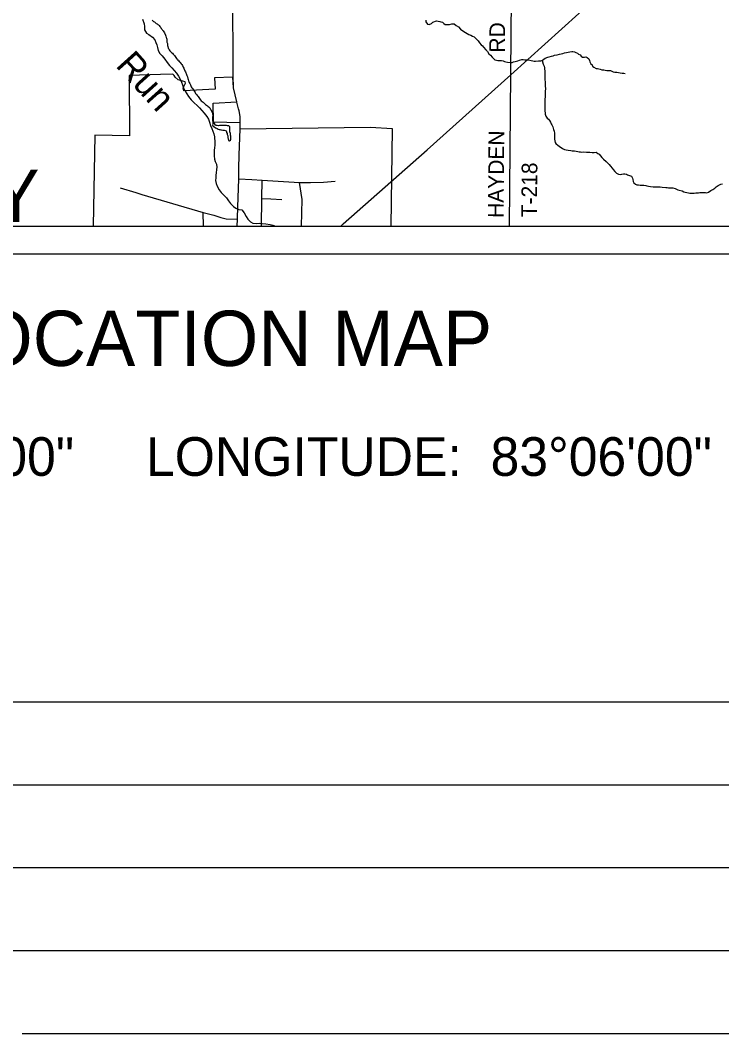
# Model space of a CAD drawing. Extents: x 36.7 to 70.7, y 0 to 22.
# Drawn here: x 41.432 to 43.973, y 11.174 to 14.842 of the extents above; entities that cross this region are included whole.
import ezdxf

# ---------------------------------------------------------------- set-up
doc = ezdxf.new("R2010")
doc.units = 0
for name, color, linetype in [('Default', 7, 'Continuous'), ('GM_X_City_Street', 7, 'Continuous'), ('GM_X_County_Text', 7, 'Continuous'), ('GM_X_Minor_Lake', 7, 'Continuous'), ('GM_X_Minor_River', 7, 'Continuous'), ('GM_X_Minor_River_Text', 7, 'Continuous'), ('GM_X_Rail_Line', 7, 'Continuous'), ('GM_X_State_Route', 7, 'Continuous'), ('GM_X_Township_Road', 7, 'Continuous'), ('GM_X_Township_Road_Text', 7, 'Continuous'), ('SH_Data', 7, 'Continuous'), ('SH_Text', 7, 'Continuous')]:
    doc.layers.add(name, color=color, linetype=linetype)

msp = doc.modelspace()

# ---------------------------------------------------------------- linework, layer by layer
at = {"layer": 'Default'}
msp.add_lwpolyline([(41.696, 14.0969), (42.7752, 14.0969), (42.7801, 14.449), (42.6989, 14.4538), (42.2284, 14.4482), (42.2286, 14.4703), (42.1324, 14.4735), (42.1311, 14.5419), (42.2166, 14.5464), (42.2043, 14.5971), (42.2017, 14.6361), (42.1352, 14.6338), (42.1378, 14.593), (42.024, 14.586), (42.0216, 14.5973), (42.0299, 14.6136), (42.0289, 14.6195), (42.0037, 14.6264), (41.9927, 14.6363), (41.9899, 14.642), (41.9846, 14.6465), (41.9394, 14.6451), (41.8268, 14.6415), (41.828, 14.4237), (41.7017, 14.4263)], close=True, dxfattribs=at)
at = {"layer": 'GM_X_City_Street'}
for p, q in [((41.7934, 14.2353), (41.8502, 14.2179)), ((42.0951, 14.0969), (42.0942, 14.1456))]:
    msp.add_line(p, q, dxfattribs=at)
for points in [[(42.2231, 14.2684), (42.2709, 14.2658), (42.308, 14.2634), (42.443, 14.2543), (42.4807, 14.255), (42.4827, 14.255)], [(42.3053, 14.0969), (42.3067, 14.1966), (42.308, 14.2634)], [(42.4509, 14.0969), (42.4529, 14.1928), (42.443, 14.2543)], [(42.4827, 14.255), (42.5306, 14.2559), (42.5727, 14.2592)], [(41.8502, 14.2179), (41.8729, 14.2109), (42.0942, 14.1456)], [(42.3067, 14.1966), (42.3395, 14.1954), (42.3796, 14.1936)], [(42.0942, 14.1456), (42.1326, 14.1361), (42.1584, 14.1275), (42.1782, 14.123), (42.2186, 14.1223)]]:
    msp.add_lwpolyline(points, dxfattribs=at)
at = {"layer": 'GM_X_Minor_Lake'}
for points in [[(42.1295, 14.4717), (42.1291, 14.4702), (42.129, 14.4668), (42.1286, 14.4634), (42.1293, 14.46)], [(42.1293, 14.46), (42.133, 14.4573), (42.1397, 14.4526), (42.1423, 14.4514), (42.1449, 14.4498), (42.1483, 14.4482), (42.1521, 14.447), (42.1547, 14.4462), (42.1581, 14.4454), (42.1611, 14.4449), (42.1657, 14.4445), (42.1702, 14.4436), (42.1739, 14.4428), (42.1773, 14.442), (42.1784, 14.4389), (42.1795, 14.4355), (42.1817, 14.432), (42.182, 14.4286), (42.1827, 14.4259), (42.1838, 14.4232), (42.1837, 14.4198), (42.1844, 14.4172), (42.185, 14.4118), (42.1857, 14.4092), (42.1868, 14.4065), (42.1898, 14.4057), (42.1933, 14.4082), (42.1945, 14.4116), (42.1946, 14.4188), (42.1943, 14.4223), (42.1937, 14.4257), (42.1937, 14.4287), (42.193, 14.4314), (42.1916, 14.4383), (42.1913, 14.4409), (42.1914, 14.4436), (42.1911, 14.447), (42.1908, 14.4504), (42.1908, 14.4531), (42.1905, 14.4557), (42.1875, 14.4592), (42.1823, 14.4601), (42.1789, 14.4609), (42.1751, 14.4613), (42.1683, 14.4615), (42.1649, 14.4612), (42.1618, 14.4609), (42.1584, 14.4609), (42.1558, 14.4606), (42.1531, 14.4606), (42.1505, 14.4603), (42.1448, 14.4604), (42.1418, 14.4613), (42.1388, 14.4625), (42.1366, 14.4659), (42.1295, 14.4717)]]:
    msp.add_lwpolyline(points, dxfattribs=at)
at = {"layer": 'GM_X_Minor_River'}
for points in [[(41.8745, 14.8458), (41.8808, 14.8294), (41.8814, 14.8188), (41.8817, 14.8067), (41.8895, 14.7956), (41.8982, 14.7909), (41.911, 14.7801), (41.9196, 14.7706), (41.9236, 14.761), (41.927, 14.7523), (41.9291, 14.7431), (41.932, 14.7325), (41.9376, 14.7214), (41.9455, 14.7126), (41.956, 14.7007), (41.9642, 14.6888), (41.9724, 14.6785), (41.9806, 14.6697), (41.9896, 14.6597), (41.9982, 14.6501), (42.0057, 14.639), (42.0109, 14.6291), (42.0161, 14.6173), (42.0194, 14.6078), (42.0234, 14.5967), (42.0294, 14.5849), (42.0349, 14.5753), (42.0409, 14.5662), (42.0506, 14.5543), (42.0623, 14.5435), (42.0724, 14.5339), (42.081, 14.5247)], [(41.9097, 14.8426), (41.9123, 14.8403), (41.9149, 14.8376), (41.9179, 14.8356), (41.9212, 14.8333), (41.9246, 14.8302), (41.9276, 14.829), (41.9298, 14.8263), (41.9324, 14.8247), (41.935, 14.8224), (41.9376, 14.8197), (41.9406, 14.8154), (41.9428, 14.8124), (41.9457, 14.8089), (41.9476, 14.8062), (41.9494, 14.8035), (41.952, 14.8004), (41.9549, 14.7969), (41.9581, 14.7878), (41.9588, 14.7847), (41.9603, 14.7798), (41.9617, 14.7767), (41.9628, 14.774), (41.9627, 14.7683), (41.963, 14.7657), (41.9633, 14.7626), (41.9644, 14.76), (41.9651, 14.7573), (41.965, 14.7539), (41.9653, 14.7504), (41.9664, 14.7466), (41.9682, 14.7413), (41.9696, 14.7382), (41.9718, 14.7344), (41.974, 14.7317), (41.9803, 14.7251), (41.9829, 14.7228), (41.9859, 14.7193), (41.9881, 14.7166), (41.9911, 14.7139), (41.9933, 14.7101), (41.9984, 14.7039), (42.001, 14.7012), (42.0032, 14.6973), (42.0062, 14.695), (42.0084, 14.6915), (42.0117, 14.6888), (42.0151, 14.6846), (42.0173, 14.6815), (42.0191, 14.6781), (42.0213, 14.675), (42.0224, 14.6723), (42.0246, 14.6681), (42.0256, 14.665), (42.0271, 14.6616), (42.0282, 14.6589), (42.03, 14.6547), (42.0314, 14.6516), (42.0325, 14.649), (42.0339, 14.6459), (42.0357, 14.6413), (42.0372, 14.6375), (42.0385, 14.6306), (42.0396, 14.6272), (42.041, 14.623), (42.0429, 14.6199), (42.0439, 14.6169), (42.0457, 14.613), (42.0472, 14.6103), (42.0487, 14.6077), (42.0497, 14.6046), (42.0516, 14.6008), (42.0537, 14.5969), (42.0567, 14.5931), (42.0589, 14.5904), (42.0607, 14.5873), (42.0633, 14.5842), (42.0651, 14.5808), (42.0673, 14.5773), (42.0688, 14.5746), (42.0714, 14.5715), (42.0743, 14.5681), (42.0758, 14.5654), (42.0784, 14.5623), (42.081, 14.5588), (42.0839, 14.5546), (42.0876, 14.5504), (42.0913, 14.5472), (42.0943, 14.5449), (42.0977, 14.5422), (42.1002, 14.5395), (42.1032, 14.5371), (42.1066, 14.534), (42.1096, 14.5321), (42.1129, 14.5297), (42.1159, 14.5278), (42.1189, 14.5243), (42.1199, 14.5216), (42.1218, 14.5189)], [(42.9005, 14.8424), (42.9016, 14.8367), (42.9072, 14.8283), (42.9136, 14.827), (42.9213, 14.8304), (42.9259, 14.8345), (42.9392, 14.8397), (42.9513, 14.8377), (42.9559, 14.8365), (42.9615, 14.8345), (42.9668, 14.8303), (42.9713, 14.8264), (42.9823, 14.8263), (42.9868, 14.8266), (42.9952, 14.8292), (43.0039, 14.8284), (43.0107, 14.823), (43.0194, 14.8179), (43.0272, 14.8091), (43.0355, 14.8033), (43.0445, 14.7975), (43.0513, 14.7941), (43.0566, 14.7902), (43.0638, 14.7879), (43.0698, 14.7848), (43.0758, 14.7813), (43.0811, 14.7767), (43.0856, 14.7717), (43.0905, 14.7671), (43.095, 14.7606), (43.1017, 14.7533), (43.1062, 14.7491), (43.1103, 14.7441), (43.1178, 14.7345), (43.1246, 14.7291), (43.1294, 14.7207), (43.1358, 14.715), (43.1414, 14.7077), (43.1467, 14.7038), (43.1508, 14.6985), (43.1568, 14.6969), (43.1617, 14.6957), (43.1667, 14.6964), (43.1746, 14.6959), (43.1807, 14.6951), (43.1864, 14.6928), (43.1909, 14.6912), (43.1966, 14.6896), (43.2076, 14.6888), (43.214, 14.6887), (43.2186, 14.6909), (43.225, 14.6924), (43.2338, 14.6945), (43.2407, 14.6971), (43.2483, 14.6993)], [(43.2483, 14.6993), (43.254, 14.6993), (43.2596, 14.6988), (43.2649, 14.6988), (43.2706, 14.6991), (43.2774, 14.6971), (43.282, 14.6959), (43.2884, 14.6947), (43.293, 14.6943), (43.2983, 14.6942), (43.3097, 14.6949), (43.3176, 14.6955), (43.3241, 14.697), (43.3329, 14.7045), (43.3428, 14.7078), (43.3481, 14.7089), (43.3565, 14.7122), (43.3622, 14.7133), (43.3668, 14.7151), (43.3767, 14.7173), (43.3847, 14.7191), (43.3968, 14.722), (43.4033, 14.7239), (43.4105, 14.7253), (43.417, 14.7264), (43.4227, 14.7278), (43.4295, 14.7285), (43.4341, 14.7285), (43.4398, 14.7276), (43.4447, 14.7257), (43.4499, 14.7222), (43.4545, 14.7195), (43.4605, 14.7168), (43.4639, 14.7114), (43.4687, 14.7083), (43.4752, 14.7087), (43.4801, 14.709), (43.485, 14.7067), (43.4911, 14.7017), (43.4944, 14.6967), (43.4951, 14.691), (43.4984, 14.6845), (43.503, 14.6807), (43.5048, 14.6757), (43.5093, 14.6719), (43.5176, 14.6676), (43.5229, 14.6668), (43.5331, 14.6644), (43.5388, 14.6628), (43.5456, 14.6624), (43.5509, 14.6615), (43.5562, 14.66), (43.5619, 14.6595), (43.5698, 14.6594), (43.5744, 14.6579), (43.58, 14.6555), (43.5853, 14.6543), (43.5929, 14.6535), (43.605, 14.6518), (43.6126, 14.6502), (43.6179, 14.6498), (43.6228, 14.649)], [(43.3228, 14.6967), (43.3266, 14.6833), (43.3292, 14.6757), (43.3306, 14.67), (43.3313, 14.665), (43.332, 14.6582), (43.3318, 14.6426), (43.3324, 14.629), (43.3327, 14.6164), (43.3334, 14.6103), (43.3337, 14.6031), (43.3339, 14.5944), (43.3334, 14.5838), (43.333, 14.5766), (43.3328, 14.5648), (43.3324, 14.5561), (43.332, 14.5246), (43.3323, 14.5189), (43.3326, 14.5128), (43.3333, 14.5067), (43.3333, 14.5022), (43.3362, 14.4945), (43.3403, 14.488), (43.3456, 14.4842), (43.3493, 14.4796), (43.3523, 14.4735), (43.3556, 14.4674), (43.3575, 14.4628), (43.3608, 14.4559), (43.3637, 14.4468), (43.3659, 14.4407), (43.3674, 14.4335), (43.3677, 14.4266), (43.3675, 14.4114), (43.3678, 14.405), (43.3696, 14.3989), (43.3726, 14.3935), (43.3775, 14.3908), (43.3847, 14.3851), (43.3907, 14.3816), (43.3959, 14.3773), (43.4039, 14.3742), (43.4088, 14.373), (43.4164, 14.3718), (43.4262, 14.3709), (43.4308, 14.3698), (43.4395, 14.3689), (43.4455, 14.3681), (43.4512, 14.3673), (43.4565, 14.3661), (43.4614, 14.3656), (43.466, 14.3648), (43.472, 14.3651), (43.483, 14.365), (43.4903, 14.3646), (43.4956, 14.3641), (43.5035, 14.3633), (43.5103, 14.3632), (43.5176, 14.3639), (43.5236, 14.36), (43.5285, 14.3569), (43.5337, 14.3512), (43.5382, 14.3455), (43.545, 14.3385), (43.5543, 14.3301), (43.5592, 14.3259), (43.5652, 14.3201), (43.5705, 14.3136), (43.5764, 14.3059), (43.5802, 14.3013), (43.5854, 14.2945), (43.5914, 14.2879), (43.5986, 14.2844), (43.6069, 14.284), (43.6115, 14.2851), (43.6172, 14.2865), (43.6217, 14.2865), (43.6274, 14.2849), (43.6319, 14.2829), (43.6391, 14.2802), (43.6459, 14.2771), (43.6496, 14.2706), (43.6503, 14.2653), (43.6518, 14.2584), (43.654, 14.2531), (43.6608, 14.2481), (43.6653, 14.2465), (43.6714, 14.2461), (43.677, 14.2453), (43.6839, 14.2448), (43.6911, 14.2447), (43.6975, 14.2439), (43.702, 14.2427), (43.7081, 14.2419), (43.7145, 14.2407), (43.724, 14.2391), (43.7502, 14.2388), (43.7577, 14.2379), (43.7699, 14.2371), (43.7748, 14.2362), (43.7805, 14.2354)], [(42.081, 14.5247), (42.0893, 14.5155), (42.0986, 14.5055), (42.1072, 14.4933), (42.1132, 14.4841), (42.1169, 14.4735), (42.1205, 14.4613), (42.1253, 14.4498), (42.1294, 14.4407), (42.1331, 14.4308), (42.1352, 14.4194), (42.1365, 14.3996), (42.1364, 14.3894), (42.1355, 14.3806), (42.1339, 14.3712), (42.1338, 14.3624), (42.1344, 14.3507), (42.1358, 14.3396), (42.138, 14.3309), (42.1428, 14.3206), (42.1438, 14.3107), (42.143, 14.3016), (42.1421, 14.2898), (42.1408, 14.2811), (42.1404, 14.2716), (42.1395, 14.2614), (42.142, 14.2515), (42.1449, 14.2412), (42.1524, 14.2278), (42.1598, 14.2183), (42.1696, 14.2091), (42.1786, 14.1987), (42.1864, 14.1884), (42.1939, 14.1788), (42.2048, 14.1681), (42.2134, 14.1615), (42.224, 14.1568), (42.2342, 14.156), (42.2425, 14.1453), (42.2503, 14.1319), (42.2566, 14.1223), (42.2656, 14.1124), (42.2743, 14.1073), (42.2875, 14.1064), (42.2974, 14.1075), (42.308, 14.1062), (42.322, 14.1049), (42.3376, 14.1021), (42.3466, 14.1001), (42.3568, 14.0969), (42.357, 14.0969)], [(42.1218, 14.5189), (42.1236, 14.5155), (42.1251, 14.5128), (42.1269, 14.5086), (42.1286, 14.5014), (42.1293, 14.4972), (42.1296, 14.4945), (42.1288, 14.4911), (42.1283, 14.4881), (42.1282, 14.4843), (42.1278, 14.4797), (42.1292, 14.4718)], [(43.7805, 14.2354), (43.7862, 14.235), (43.7915, 14.2353), (43.796, 14.2349), (43.8043, 14.2325), (43.8142, 14.2286), (43.8187, 14.227), (43.8293, 14.2239), (43.8361, 14.2212), (43.841, 14.2196), (43.8463, 14.2184), (43.852, 14.2172), (43.8573, 14.216), (43.8671, 14.2155), (43.8736, 14.2166), (43.8796, 14.2173), (43.8884, 14.2176), (43.8941, 14.2183), (43.907, 14.2181), (43.9138, 14.2181), (43.9195, 14.2176), (43.9244, 14.2195), (43.9336, 14.2254), (43.9405, 14.2292), (43.9474, 14.2344), (43.9531, 14.2389), (43.96, 14.2434), (43.9649, 14.2464), (43.9695, 14.2486), (43.976, 14.25)]]:
    msp.add_lwpolyline(points, dxfattribs=at)
at = {"layer": 'GM_X_Rail_Line'}
msp.add_lwpolyline([(42.5932, 14.0969), (42.6018, 14.1045), (42.9057, 14.3723), (43.2092, 14.6439), (43.5174, 14.9236), (43.8818, 15.2533), (44.2007, 15.5398), (44.9423, 16.2118), (45.4899, 16.7019), (45.5934, 16.801)], dxfattribs=at)
at = {"layer": 'GM_X_State_Route'}
for points in [[(42.2026, 14.6407), (42.202, 14.9604)], [(42.2152, 14.5525), (42.2046, 14.5965), (42.2026, 14.6407)], [(42.2247, 14.5136), (42.2228, 14.5218), (42.2204, 14.5313), (42.2169, 14.5459), (42.2152, 14.5525)], [(42.2289, 14.4738), (42.2291, 14.4919), (42.2261, 14.5075), (42.2247, 14.5136)], [(42.2253, 14.3545), (42.2286, 14.4476), (42.2287, 14.4544)], [(42.2287, 14.4544), (42.2289, 14.4698), (42.2289, 14.4738)], [(42.2187, 14.1252), (42.2199, 14.1659), (42.2231, 14.2684), (42.2239, 14.3127), (42.225, 14.3475), (42.2253, 14.3545)], [(42.2182, 14.0969), (42.2186, 14.1223), (42.2187, 14.1252)]]:
    msp.add_lwpolyline(points, dxfattribs=at)
at = {"layer": 'GM_X_Township_Road'}
msp.add_line((43.2035, 14.0969), (43.2111, 14.9295), dxfattribs=at)
msp.add_lwpolyline([(41.174, 14.9671), (41.1522, 14.4699), (41.1418, 14.0969), (45.5934, 14.0969), (45.5934, 19.8832)], dxfattribs=at)
at = {"layer": 'SH_Data'}
for p, q in [((38.7934, 14.0969), (45.5934, 14.0969)), ((38.6934, 13.9969), (45.6934, 13.9969)), ((44.3934, 12.3736), (41.1871, 12.3736)), ((44.3934, 12.0736), (40.6829, 12.0736)), ((44.3934, 11.7736), (40.3126, 11.7736)), ((44.3934, 11.4736), (40.0222, 11.4736)), ((44.3934, 11.1736), (41.4387, 11.1736))]:
    msp.add_line(p, q, dxfattribs=at)

# ---------------------------------------------------------------- texts
at = {"layer": 'GM_X_County_Text'}
msp.add_text('SANDUSKY COUNTY', height=0.189394, rotation=0.0833, dxfattribs=at).set_placement((38.9687, 14.1078))
at = {"layer": 'GM_X_Minor_River_Text'}
msp.add_text('Run', height=0.09476, rotation=312.0477, dxfattribs=at).set_placement((41.7744, 14.6765))
at = {"layer": 'GM_X_Township_Road_Text'}
for s, rotation, p in [('RD', 89.5063, (43.1875, 14.7245)), ('HAYDEN', 89.512, (43.1825, 14.1262)), ('T-218', 89.4386, (43.3032, 14.1284))]:
    msp.add_text(s, height=0.05682, rotation=rotation, dxfattribs=at).set_placement(p)
at = {"layer": 'SH_Text'}
for s, height, p in [('LOCATION MAP', 0.2, (41.1203, 13.5907)), ('LATITUDE:  41°24\'00"     LONGITUDE:  83°06\'00"', 0.14, (39.7644, 13.1928))]:
    msp.add_text(s, height=height, dxfattribs=at).set_placement(p)

doc.saveas('drawing.dxf')
